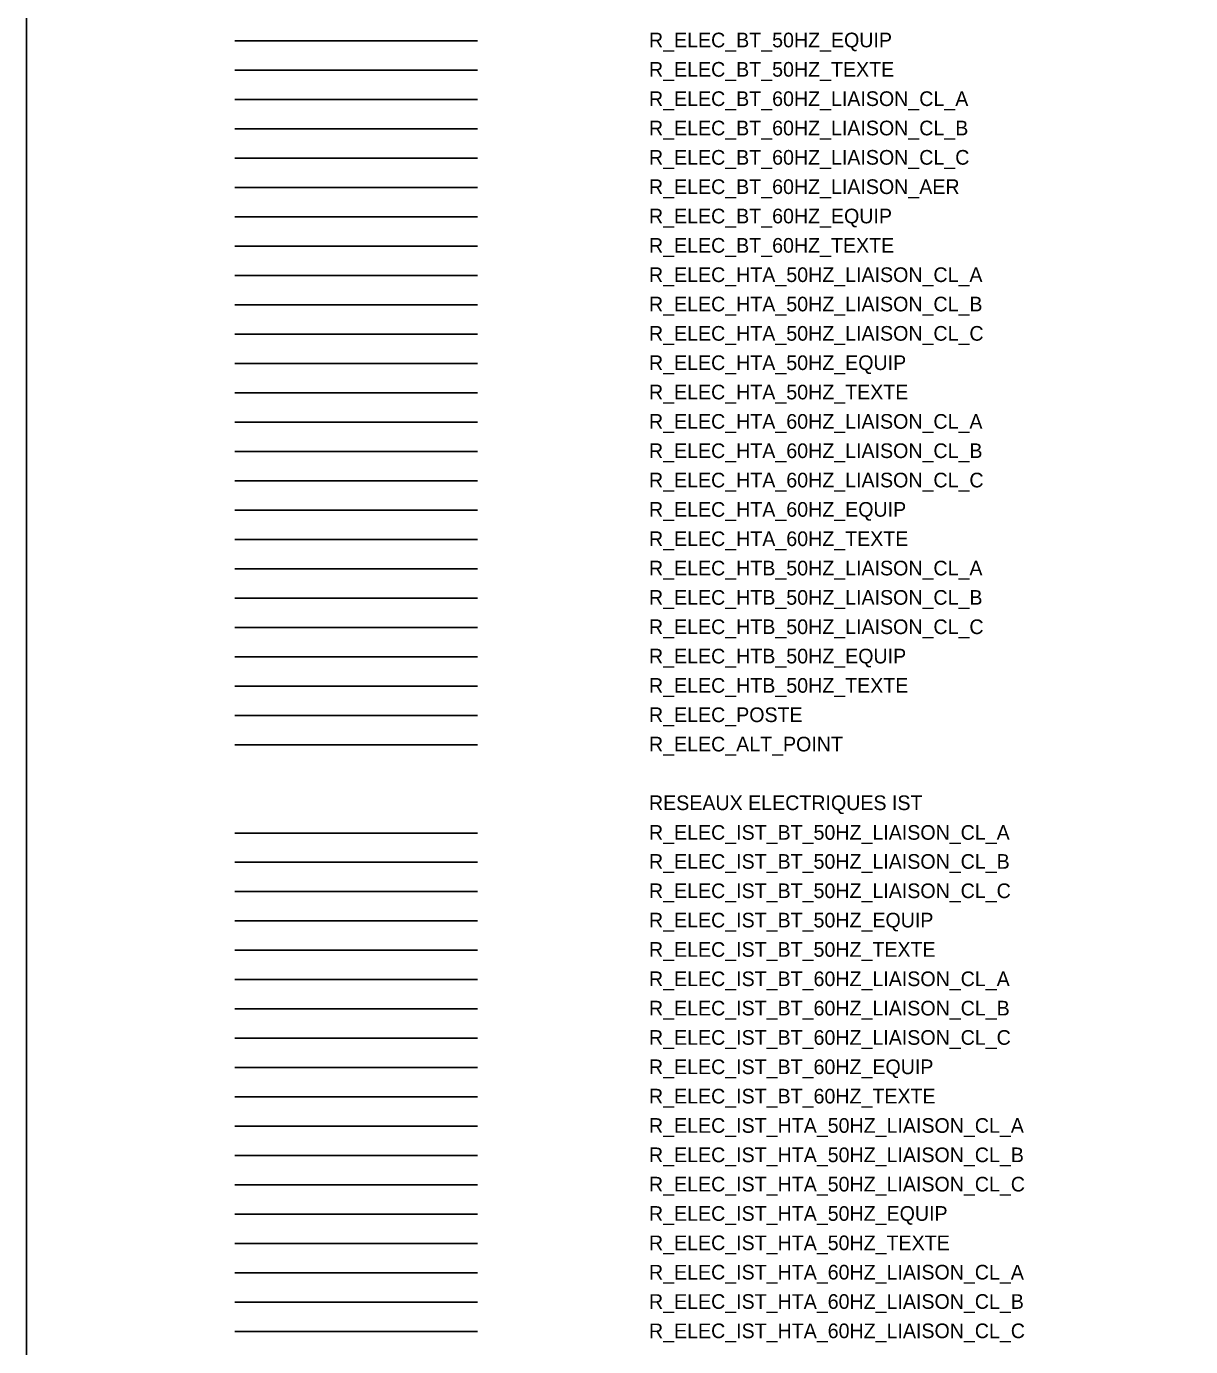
# Model space of a CAD drawing. Extents: x -60 to 214, y -380 to -21.
# Drawn here: x 33.07 to 72.77, y -110.94 to -65.94 of the extents above; entities that cross this region are included whole.
import ezdxf

# ---------------------------------------------------------------- set-up
doc = ezdxf.new("R2010")
doc.units = 0
for name, color, linetype in [('Default', 7, 'Continuous'), ('DH_TEXTE', 7, 'Continuous'), ('R_ELEC_ALT_POINT', 7, 'Continuous'), ('R_ELEC_BT_50HZ_EQUIP', 7, 'Continuous'), ('R_ELEC_BT_50HZ_TEXTE', 7, 'Continuous'), ('R_ELEC_BT_60HZ_EQUIP', 7, 'Continuous'), ('R_ELEC_BT_60HZ_LIAISON_CL_A', 7, 'Continuous'), ('R_ELEC_BT_60HZ_LIAISON_CL_B', 7, 'Continuous'), ('R_ELEC_BT_60HZ_LIAISON_CL_C', 7, 'Continuous'), ('R_ELEC_BT_60HZ_TEXTE', 7, 'Continuous'), ('R_ELEC_HTA_50HZ_EQUIP', 7, 'Continuous'), ('R_ELEC_HTA_50HZ_LIAISON_CL_A', 7, 'Continuous'), ('R_ELEC_HTA_50HZ_LIAISON_CL_B', 7, 'Continuous'), ('R_ELEC_HTA_50HZ_LIAISON_CL_C', 7, 'Continuous'), ('R_ELEC_HTA_50HZ_TEXTE', 7, 'Continuous'), ('R_ELEC_HTA_60HZ_EQUIP', 7, 'Continuous'), ('R_ELEC_HTA_60HZ_LIAISON_CL_A', 7, 'Continuous'), ('R_ELEC_HTA_60HZ_LIAISON_CL_B', 7, 'Continuous'), ('R_ELEC_HTA_60HZ_LIAISON_CL_C', 7, 'Continuous'), ('R_ELEC_HTA_60HZ_TEXTE', 7, 'Continuous'), ('R_ELEC_HTB_50HZ_EQUIP', 7, 'Continuous'), ('R_ELEC_HTB_50HZ_LIAISON_CL_A', 7, 'Continuous'), ('R_ELEC_HTB_50HZ_LIAISON_CL_B', 7, 'Continuous'), ('R_ELEC_HTB_50HZ_LIAISON_CL_C', 7, 'Continuous'), ('R_ELEC_HTB_50HZ_TEXTE', 7, 'Continuous'), ('R_ELEC_IST_BT_50HZ_EQUIP', 7, 'Continuous'), ('R_ELEC_IST_BT_50HZ_LIAISON_CL_A', 7, 'Continuous'), ('R_ELEC_IST_BT_50HZ_LIAISON_CL_B', 7, 'Continuous'), ('R_ELEC_IST_BT_50HZ_LIAISON_CL_C', 7, 'Continuous'), ('R_ELEC_IST_BT_50HZ_TEXTE', 7, 'Continuous'), ('R_ELEC_IST_BT_60HZ_EQUIP', 7, 'Continuous'), ('R_ELEC_IST_BT_60HZ_LIAISON_CL_A', 7, 'Continuous'), ('R_ELEC_IST_BT_60HZ_LIAISON_CL_B', 7, 'Continuous'), ('R_ELEC_IST_BT_60HZ_LIAISON_CL_C', 7, 'Continuous'), ('R_ELEC_IST_BT_60HZ_TEXTE', 7, 'Continuous'), ('R_ELEC_IST_HTA_50HZ_EQUIP', 7, 'Continuous'), ('R_ELEC_IST_HTA_50HZ_LIAISON_CL_A', 7, 'Continuous'), ('R_ELEC_IST_HTA_50HZ_LIAISON_CL_B', 7, 'Continuous'), ('R_ELEC_IST_HTA_50HZ_LIAISON_CL_C', 7, 'Continuous'), ('R_ELEC_IST_HTA_50HZ_TEXTE', 7, 'Continuous'), ('R_ELEC_IST_HTA_60HZ_LIAISON_CL_A', 7, 'Continuous'), ('R_ELEC_IST_HTA_60HZ_LIAISON_CL_B', 7, 'Continuous'), ('R_ELEC_IST_HTA_60HZ_LIAISON_CL_C', 7, 'Continuous'), ('R_ELEC_POSTE', 7, 'Continuous')]:
    doc.layers.add(name, color=color, linetype=linetype)

msp = doc.modelspace()

# ---------------------------------------------------------------- linework, layer by layer
at = {"layer": 'Default'}
msp.add_line((40.178, -71.429), (48.457, -71.429), dxfattribs=at)
msp.add_lwpolyline([(114.838, -25.727), (33.073, -25.727), (33.073, -380.216), (114.838, -380.216)], close=True, dxfattribs=at)
at = {"layer": 'R_ELEC_ALT_POINT'}
msp.add_line((40.178, -90.429), (48.457, -90.429), dxfattribs=at)
at = {"layer": 'R_ELEC_BT_50HZ_EQUIP'}
msp.add_line((40.178, -66.429), (48.457, -66.429), dxfattribs=at)
at = {"layer": 'R_ELEC_BT_50HZ_TEXTE'}
msp.add_line((40.178, -67.429), (48.457, -67.429), dxfattribs=at)
at = {"layer": 'R_ELEC_BT_60HZ_EQUIP'}
msp.add_line((40.178, -72.429), (48.457, -72.429), dxfattribs=at)
at = {"layer": 'R_ELEC_BT_60HZ_LIAISON_CL_A'}
msp.add_line((40.178, -68.429), (48.457, -68.429), dxfattribs=at)
at = {"layer": 'R_ELEC_BT_60HZ_LIAISON_CL_B'}
msp.add_line((40.178, -69.429), (48.457, -69.429), dxfattribs=at)
at = {"layer": 'R_ELEC_BT_60HZ_LIAISON_CL_C'}
msp.add_line((40.178, -70.429), (48.457, -70.429), dxfattribs=at)
at = {"layer": 'R_ELEC_BT_60HZ_TEXTE'}
msp.add_line((40.178, -73.429), (48.457, -73.429), dxfattribs=at)
at = {"layer": 'R_ELEC_HTA_50HZ_EQUIP'}
msp.add_line((40.178, -77.429), (48.457, -77.429), dxfattribs=at)
at = {"layer": 'R_ELEC_HTA_50HZ_LIAISON_CL_A'}
msp.add_line((40.178, -74.429), (48.457, -74.429), dxfattribs=at)
at = {"layer": 'R_ELEC_HTA_50HZ_LIAISON_CL_B'}
msp.add_line((40.178, -75.429), (48.457, -75.429), dxfattribs=at)
at = {"layer": 'R_ELEC_HTA_50HZ_LIAISON_CL_C'}
msp.add_line((40.178, -76.429), (48.457, -76.429), dxfattribs=at)
at = {"layer": 'R_ELEC_HTA_50HZ_TEXTE'}
msp.add_line((40.178, -78.429), (48.457, -78.429), dxfattribs=at)
at = {"layer": 'R_ELEC_HTA_60HZ_EQUIP'}
msp.add_line((40.178, -82.429), (48.457, -82.429), dxfattribs=at)
at = {"layer": 'R_ELEC_HTA_60HZ_LIAISON_CL_A'}
msp.add_line((40.178, -79.429), (48.457, -79.429), dxfattribs=at)
at = {"layer": 'R_ELEC_HTA_60HZ_LIAISON_CL_B'}
msp.add_line((40.178, -80.429), (48.457, -80.429), dxfattribs=at)
at = {"layer": 'R_ELEC_HTA_60HZ_LIAISON_CL_C'}
msp.add_line((40.178, -81.429), (48.457, -81.429), dxfattribs=at)
at = {"layer": 'R_ELEC_HTA_60HZ_TEXTE'}
msp.add_line((40.178, -83.429), (48.457, -83.429), dxfattribs=at)
at = {"layer": 'R_ELEC_HTB_50HZ_EQUIP'}
msp.add_line((40.178, -87.429), (48.457, -87.429), dxfattribs=at)
at = {"layer": 'R_ELEC_HTB_50HZ_LIAISON_CL_A'}
msp.add_line((40.178, -84.429), (48.457, -84.429), dxfattribs=at)
at = {"layer": 'R_ELEC_HTB_50HZ_LIAISON_CL_B'}
msp.add_line((40.178, -85.429), (48.457, -85.429), dxfattribs=at)
at = {"layer": 'R_ELEC_HTB_50HZ_LIAISON_CL_C'}
msp.add_line((40.178, -86.429), (48.457, -86.429), dxfattribs=at)
at = {"layer": 'R_ELEC_HTB_50HZ_TEXTE'}
msp.add_line((40.178, -88.429), (48.457, -88.429), dxfattribs=at)
at = {"layer": 'R_ELEC_IST_BT_50HZ_EQUIP'}
msp.add_line((40.178, -96.429), (48.457, -96.429), dxfattribs=at)
at = {"layer": 'R_ELEC_IST_BT_50HZ_LIAISON_CL_A'}
msp.add_line((40.178, -93.44), (48.457, -93.44), dxfattribs=at)
at = {"layer": 'R_ELEC_IST_BT_50HZ_LIAISON_CL_B'}
msp.add_line((40.178, -94.429), (48.457, -94.429), dxfattribs=at)
at = {"layer": 'R_ELEC_IST_BT_50HZ_LIAISON_CL_C'}
msp.add_line((40.178, -95.429), (48.457, -95.429), dxfattribs=at)
at = {"layer": 'R_ELEC_IST_BT_50HZ_TEXTE'}
msp.add_line((40.178, -97.429), (48.457, -97.429), dxfattribs=at)
at = {"layer": 'R_ELEC_IST_BT_60HZ_EQUIP'}
msp.add_line((40.178, -101.429), (48.457, -101.429), dxfattribs=at)
at = {"layer": 'R_ELEC_IST_BT_60HZ_LIAISON_CL_A'}
msp.add_line((40.178, -98.429), (48.457, -98.429), dxfattribs=at)
at = {"layer": 'R_ELEC_IST_BT_60HZ_LIAISON_CL_B'}
msp.add_line((40.178, -99.429), (48.457, -99.429), dxfattribs=at)
at = {"layer": 'R_ELEC_IST_BT_60HZ_LIAISON_CL_C'}
msp.add_line((40.178, -100.429), (48.457, -100.429), dxfattribs=at)
at = {"layer": 'R_ELEC_IST_BT_60HZ_TEXTE'}
msp.add_line((40.178, -102.429), (48.457, -102.429), dxfattribs=at)
at = {"layer": 'R_ELEC_IST_HTA_50HZ_EQUIP'}
msp.add_line((40.178, -106.429), (48.457, -106.429), dxfattribs=at)
at = {"layer": 'R_ELEC_IST_HTA_50HZ_LIAISON_CL_A'}
msp.add_line((40.178, -103.429), (48.457, -103.429), dxfattribs=at)
at = {"layer": 'R_ELEC_IST_HTA_50HZ_LIAISON_CL_B'}
msp.add_line((40.178, -104.429), (48.457, -104.429), dxfattribs=at)
at = {"layer": 'R_ELEC_IST_HTA_50HZ_LIAISON_CL_C'}
msp.add_line((40.178, -105.429), (48.457, -105.429), dxfattribs=at)
at = {"layer": 'R_ELEC_IST_HTA_50HZ_TEXTE'}
msp.add_line((40.178, -107.429), (48.457, -107.429), dxfattribs=at)
at = {"layer": 'R_ELEC_IST_HTA_60HZ_LIAISON_CL_A'}
msp.add_line((40.178, -108.429), (48.457, -108.429), dxfattribs=at)
at = {"layer": 'R_ELEC_IST_HTA_60HZ_LIAISON_CL_B'}
msp.add_line((40.178, -109.429), (48.457, -109.429), dxfattribs=at)
at = {"layer": 'R_ELEC_IST_HTA_60HZ_LIAISON_CL_C'}
msp.add_line((40.178, -110.429), (48.457, -110.429), dxfattribs=at)
at = {"layer": 'R_ELEC_POSTE'}
msp.add_line((40.178, -89.429), (48.457, -89.429), dxfattribs=at)

# ---------------------------------------------------------------- texts
at = {"layer": 'DH_TEXTE'}
for s, p in [('R_ELEC_BT_60HZ_LIAISON_AER ', (54.301, -71.655)), ('RESEAUX ELECTRIQUES IST ', (54.301, -92.655))]:
    msp.add_text(s, height=0.5, dxfattribs=at).set_placement(p)
at = {"layer": 'R_ELEC_ALT_POINT'}
msp.add_text('R_ELEC_ALT_POINT  ', height=0.5, dxfattribs=at).set_placement((54.301, -90.655))
at = {"layer": 'R_ELEC_BT_50HZ_EQUIP'}
msp.add_text('R_ELEC_BT_50HZ_EQUIP ', height=0.5, dxfattribs=at).set_placement((54.301, -66.655))
at = {"layer": 'R_ELEC_BT_50HZ_TEXTE'}
msp.add_text('R_ELEC_BT_50HZ_TEXTE ', height=0.5, dxfattribs=at).set_placement((54.301, -67.655))
at = {"layer": 'R_ELEC_BT_60HZ_EQUIP'}
msp.add_text('R_ELEC_BT_60HZ_EQUIP ', height=0.5, dxfattribs=at).set_placement((54.301, -72.655))
at = {"layer": 'R_ELEC_BT_60HZ_LIAISON_CL_A'}
msp.add_text('R_ELEC_BT_60HZ_LIAISON_CL_A ', height=0.5, dxfattribs=at).set_placement((54.301, -68.655))
at = {"layer": 'R_ELEC_BT_60HZ_LIAISON_CL_B'}
msp.add_text('R_ELEC_BT_60HZ_LIAISON_CL_B ', height=0.5, dxfattribs=at).set_placement((54.301, -69.655))
at = {"layer": 'R_ELEC_BT_60HZ_LIAISON_CL_C'}
msp.add_text('R_ELEC_BT_60HZ_LIAISON_CL_C ', height=0.5, dxfattribs=at).set_placement((54.301, -70.655))
at = {"layer": 'R_ELEC_BT_60HZ_TEXTE'}
msp.add_text('R_ELEC_BT_60HZ_TEXTE ', height=0.5, dxfattribs=at).set_placement((54.301, -73.655))
at = {"layer": 'R_ELEC_HTA_50HZ_EQUIP'}
msp.add_text('R_ELEC_HTA_50HZ_EQUIP ', height=0.5, dxfattribs=at).set_placement((54.301, -77.655))
at = {"layer": 'R_ELEC_HTA_50HZ_LIAISON_CL_A'}
msp.add_text('R_ELEC_HTA_50HZ_LIAISON_CL_A ', height=0.5, dxfattribs=at).set_placement((54.301, -74.655))
at = {"layer": 'R_ELEC_HTA_50HZ_LIAISON_CL_B'}
msp.add_text('R_ELEC_HTA_50HZ_LIAISON_CL_B ', height=0.5, dxfattribs=at).set_placement((54.301, -75.655))
at = {"layer": 'R_ELEC_HTA_50HZ_LIAISON_CL_C'}
msp.add_text('R_ELEC_HTA_50HZ_LIAISON_CL_C ', height=0.5, dxfattribs=at).set_placement((54.301, -76.655))
at = {"layer": 'R_ELEC_HTA_50HZ_TEXTE'}
msp.add_text('R_ELEC_HTA_50HZ_TEXTE ', height=0.5, dxfattribs=at).set_placement((54.301, -78.655))
at = {"layer": 'R_ELEC_HTA_60HZ_EQUIP'}
msp.add_text('R_ELEC_HTA_60HZ_EQUIP ', height=0.5, dxfattribs=at).set_placement((54.301, -82.655))
at = {"layer": 'R_ELEC_HTA_60HZ_LIAISON_CL_A'}
msp.add_text('R_ELEC_HTA_60HZ_LIAISON_CL_A ', height=0.5, dxfattribs=at).set_placement((54.301, -79.655))
at = {"layer": 'R_ELEC_HTA_60HZ_LIAISON_CL_B'}
msp.add_text('R_ELEC_HTA_60HZ_LIAISON_CL_B ', height=0.5, dxfattribs=at).set_placement((54.301, -80.655))
at = {"layer": 'R_ELEC_HTA_60HZ_LIAISON_CL_C'}
msp.add_text('R_ELEC_HTA_60HZ_LIAISON_CL_C ', height=0.5, dxfattribs=at).set_placement((54.301, -81.655))
at = {"layer": 'R_ELEC_HTA_60HZ_TEXTE'}
msp.add_text('R_ELEC_HTA_60HZ_TEXTE ', height=0.5, dxfattribs=at).set_placement((54.301, -83.655))
at = {"layer": 'R_ELEC_HTB_50HZ_EQUIP'}
msp.add_text('R_ELEC_HTB_50HZ_EQUIP ', height=0.5, dxfattribs=at).set_placement((54.301, -87.655))
at = {"layer": 'R_ELEC_HTB_50HZ_LIAISON_CL_A'}
msp.add_text('R_ELEC_HTB_50HZ_LIAISON_CL_A ', height=0.5, dxfattribs=at).set_placement((54.301, -84.655))
at = {"layer": 'R_ELEC_HTB_50HZ_LIAISON_CL_B'}
msp.add_text('R_ELEC_HTB_50HZ_LIAISON_CL_B ', height=0.5, dxfattribs=at).set_placement((54.301, -85.655))
at = {"layer": 'R_ELEC_HTB_50HZ_LIAISON_CL_C'}
msp.add_text('R_ELEC_HTB_50HZ_LIAISON_CL_C ', height=0.5, dxfattribs=at).set_placement((54.301, -86.655))
at = {"layer": 'R_ELEC_HTB_50HZ_TEXTE'}
msp.add_text('R_ELEC_HTB_50HZ_TEXTE ', height=0.5, dxfattribs=at).set_placement((54.301, -88.655))
at = {"layer": 'R_ELEC_IST_BT_50HZ_EQUIP'}
msp.add_text('R_ELEC_IST_BT_50HZ_EQUIP ', height=0.5, dxfattribs=at).set_placement((54.301, -96.655))
at = {"layer": 'R_ELEC_IST_BT_50HZ_LIAISON_CL_A'}
msp.add_text('R_ELEC_IST_BT_50HZ_LIAISON_CL_A ', height=0.5, dxfattribs=at).set_placement((54.301, -93.666))
at = {"layer": 'R_ELEC_IST_BT_50HZ_LIAISON_CL_B'}
msp.add_text('R_ELEC_IST_BT_50HZ_LIAISON_CL_B ', height=0.5, dxfattribs=at).set_placement((54.301, -94.655))
at = {"layer": 'R_ELEC_IST_BT_50HZ_LIAISON_CL_C'}
msp.add_text('R_ELEC_IST_BT_50HZ_LIAISON_CL_C ', height=0.5, dxfattribs=at).set_placement((54.301, -95.655))
at = {"layer": 'R_ELEC_IST_BT_50HZ_TEXTE'}
msp.add_text('R_ELEC_IST_BT_50HZ_TEXTE ', height=0.5, dxfattribs=at).set_placement((54.301, -97.655))
at = {"layer": 'R_ELEC_IST_BT_60HZ_EQUIP'}
msp.add_text('R_ELEC_IST_BT_60HZ_EQUIP ', height=0.5, dxfattribs=at).set_placement((54.301, -101.655))
at = {"layer": 'R_ELEC_IST_BT_60HZ_LIAISON_CL_A'}
msp.add_text('R_ELEC_IST_BT_60HZ_LIAISON_CL_A ', height=0.5, dxfattribs=at).set_placement((54.301, -98.655))
at = {"layer": 'R_ELEC_IST_BT_60HZ_LIAISON_CL_B'}
msp.add_text('R_ELEC_IST_BT_60HZ_LIAISON_CL_B ', height=0.5, dxfattribs=at).set_placement((54.301, -99.655))
at = {"layer": 'R_ELEC_IST_BT_60HZ_LIAISON_CL_C'}
msp.add_text('R_ELEC_IST_BT_60HZ_LIAISON_CL_C ', height=0.5, dxfattribs=at).set_placement((54.301, -100.655))
at = {"layer": 'R_ELEC_IST_BT_60HZ_TEXTE'}
msp.add_text('R_ELEC_IST_BT_60HZ_TEXTE ', height=0.5, dxfattribs=at).set_placement((54.301, -102.655))
at = {"layer": 'R_ELEC_IST_HTA_50HZ_EQUIP'}
msp.add_text('R_ELEC_IST_HTA_50HZ_EQUIP ', height=0.5, dxfattribs=at).set_placement((54.301, -106.655))
at = {"layer": 'R_ELEC_IST_HTA_50HZ_LIAISON_CL_A'}
msp.add_text('R_ELEC_IST_HTA_50HZ_LIAISON_CL_A ', height=0.5, dxfattribs=at).set_placement((54.301, -103.655))
at = {"layer": 'R_ELEC_IST_HTA_50HZ_LIAISON_CL_B'}
msp.add_text('R_ELEC_IST_HTA_50HZ_LIAISON_CL_B ', height=0.5, dxfattribs=at).set_placement((54.301, -104.655))
at = {"layer": 'R_ELEC_IST_HTA_50HZ_LIAISON_CL_C'}
msp.add_text('R_ELEC_IST_HTA_50HZ_LIAISON_CL_C ', height=0.5, dxfattribs=at).set_placement((54.301, -105.655))
at = {"layer": 'R_ELEC_IST_HTA_50HZ_TEXTE'}
msp.add_text('R_ELEC_IST_HTA_50HZ_TEXTE ', height=0.5, dxfattribs=at).set_placement((54.301, -107.655))
at = {"layer": 'R_ELEC_IST_HTA_60HZ_LIAISON_CL_A'}
msp.add_text('R_ELEC_IST_HTA_60HZ_LIAISON_CL_A ', height=0.5, dxfattribs=at).set_placement((54.301, -108.655))
at = {"layer": 'R_ELEC_IST_HTA_60HZ_LIAISON_CL_B'}
msp.add_text('R_ELEC_IST_HTA_60HZ_LIAISON_CL_B ', height=0.5, dxfattribs=at).set_placement((54.301, -109.655))
at = {"layer": 'R_ELEC_IST_HTA_60HZ_LIAISON_CL_C'}
msp.add_text('R_ELEC_IST_HTA_60HZ_LIAISON_CL_C ', height=0.5, dxfattribs=at).set_placement((54.301, -110.655))
at = {"layer": 'R_ELEC_POSTE'}
msp.add_text('R_ELEC_POSTE ', height=0.5, dxfattribs=at).set_placement((54.301, -89.655))

doc.saveas('drawing.dxf')
